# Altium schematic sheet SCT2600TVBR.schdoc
size 127 x 101 mm
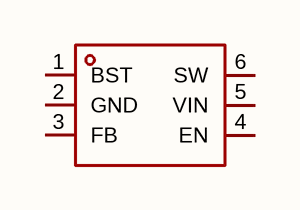
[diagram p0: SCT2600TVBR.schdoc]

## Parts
U?  sct2600tvbr  [SOT-23-6_L2.9-W1.6-P0.95-LS2.8-TL]  (value not drawn)

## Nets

Not connected (* = marked no-connect by the designer): U? 1(BST) 2(GND) 3(FB) 4(EN) 5(VIN) 6(SW)

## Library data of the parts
U? = sct2600tvbr: 功能类型:降压型;工作电压:4.5V~60V;输出电压:765mV~57V;输出电流:600mA;输出类型:可调;; Manufacturer: SCT(芯洲科技); AddInBom: yes; ModelId: 18da8f6c14a34920b3e136b5c401a119; ModelName: SOT-23-6_L2.9-W1.6-H1.5-LS2.8-P0.95; ModelTransform: 110.73671,114.173,0,0,0,0,0,0,0; Function: 降压型; Output Current: 600mA; Frequency - Switching: 2.1MHz; Synchronous Rectifier: 否; Number of Outputs: 1; Topology: 降压式; Quiescent Current: 80uA; Switch tube (built-in/external): 内置; Output Type: 可调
